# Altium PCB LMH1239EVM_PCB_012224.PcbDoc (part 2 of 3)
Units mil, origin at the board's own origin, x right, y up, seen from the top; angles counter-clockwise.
Board outline 4000 x 4500 mil, 4 copper layers (Top Layer, L02_GND, L03_PWR, Bottom Layer), stack 61.395 mil thick; 161 components, 103 nets, 483 pads, 593 vias.
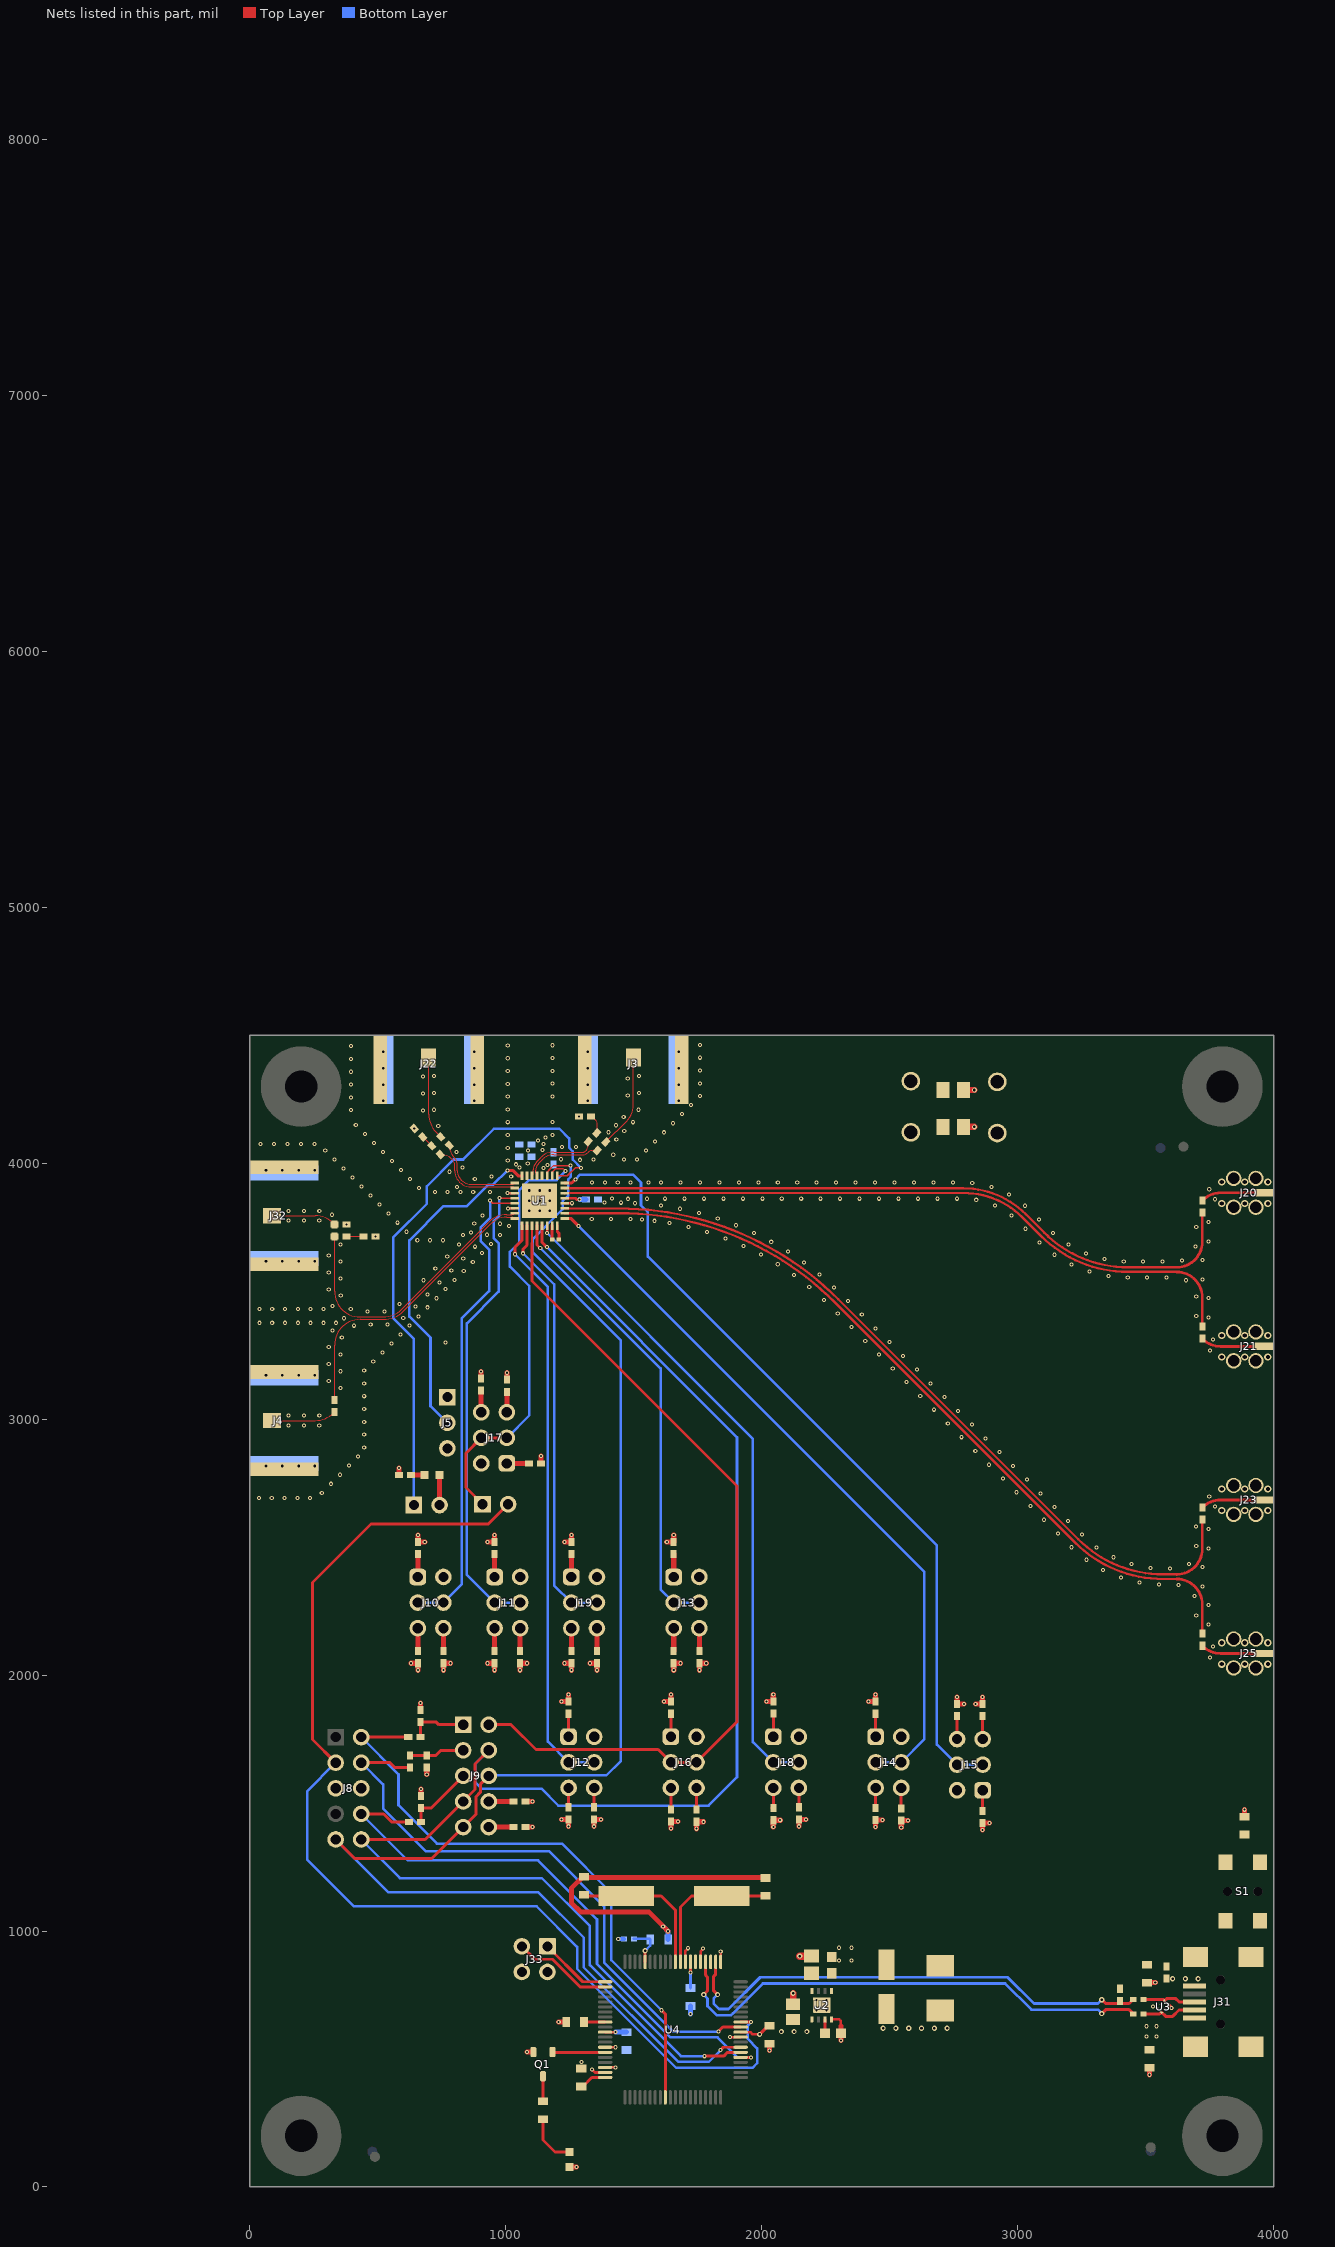
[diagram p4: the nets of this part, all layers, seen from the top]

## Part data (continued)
U3: "ESD-Protection Array for High-Speed Data Interfaces, 4 Channels, -40 to +85 degC, 6-pin SON (DRY), Green (RoHS & no Sb/Br)", Alternate Manufacturer="Texas Instruments", Alternate PartNumber=Equivalent, Breakdown Voltage(Min)(V)=6, IO Capacitance(Typ)(pF)=1.6, IO Leakage Current(nA)=1, Supplier Part Number 1=296-23618-2-ND
U4: "25 MHz Mixed Signal Microcontroller with 128 KB Flash, 8192 B SRAM and 63 GPIOs, -40 to 85 degC, 80-pin QFP (PN), Green (RoHS & no Sb/Br)", Alternate Manufacturer="Texas Instruments", Alternate PartNumber=Equivalent, Frequency(MHz)=25, Pin/Package="0DIESALE, 80LQFP", Temp Sensor=Yes
Y1: "Crystal, 24.000MHz, 20pF, SMD", Frequency=24MHz, Frequency Stability=±50ppm, Manufacturer="ECS Inc.", Supplier Part Number 1=XC1255CT-ND
ZZ2 ZZ3 ZZ4 ZZ5 ZZ6 ZZ7 ZZ8 ZZ9 ZZ10 ZZ11 ZZ12 ZZ13: library part AssemblyNote, "Place Shunt JP_N on pin 1-2"

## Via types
v1: diameter 16, hole 8, Top Layer to Bottom Layer, tented both sides, 278 vias
v2: diameter 16, hole 8.1, Top Layer to Bottom Layer, tented both sides, 224 vias
v3: diameter 20, hole 10, Top Layer to Bottom Layer, tented both sides, 54 vias
v4: diameter 28, hole 16, Top Layer to Bottom Layer, tented both sides, 24 vias
v5: diameter 20, hole 10.1, Top Layer to Bottom Layer, tented both sides, 9 vias
v6: diameter 19.68, hole 7.87, Top Layer to Bottom Layer, tented both sides, 4 vias

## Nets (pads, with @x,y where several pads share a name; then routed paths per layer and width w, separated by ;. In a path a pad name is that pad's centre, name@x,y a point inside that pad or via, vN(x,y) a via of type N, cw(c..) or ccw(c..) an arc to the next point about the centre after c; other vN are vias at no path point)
3P3V: C21.2 C32.2 C34.2 D3.1 J8.5 R1.2 R2.2 R36.1 U2.1 U4.11 U4.18 U4.50 | length 358.1
  Top Layer w10: U4.18@1387.84,467.36 v1(1428.72,467.36) ; U4.11@1387.84,605.16 v1(1428.72,605.16) ; U4.50@1917.36,604.97 1955.33,604.97 1963.9,596.4 v3(1991.8,596.4)
  Top Layer w12: v3(1991.8,596.4) 2025.4,630 C34.2@2030,630
  Top Layer w20: R2.2@1077.46,1406.52 v1(1104.58,1406.52) ; R1.2@1077.46,1506.52 v1(1104.58,1506.52) ; D3.1@1249.46,77.53 v1(1276.58,77.53)
  Bottom Layer w15: v1(1439.14,969.31) R36.1@1461.26,969.31
  Bottom Layer w20: v1(1428.72,605.16) C32.2@1471.5,605.16
  other v3: 2076.5,607.4 2126.5,607.4 2176.5,607.4
DM: R31.1 U4.64 | length 1979.8
  Top Layer w11.98: v3(1773.2,751.56) 1788.24,766.6 1788.24,819.99 1780.55,827.68 U4.64@1780.55,879.76 ; v3(3328.66,677.72) 3343.7,692.75 3435.43,692.75 R31.1@3451.73,676.46
  Bottom Layer w10.57: v3(1773.2,751.56) 1788.24,736.53 1788.24,706.84 1816.54,678.53 1823.57,671.5 1880.08,671.5 1887.11,678.53 2004.1,795.52 2951.04,795.52 3053.8,692.75 3313.63,692.75 v3(3328.66,677.72)
DP: R32.1 R33.1 U4.62 | length 1940.1
  Top Layer w11.98: U4.62@1819.92,879.76 1819.92,830.85 1812.24,823.17 1812.24,766.6 v3(1827.27,751.56) ; v3(3328.66,731.79) 3343.7,716.75 3435.43,716.75 R32.1@3451.73,733.05
  Bottom Layer w10.57: v3(1827.27,751.56) 1812.24,736.53 1812.24,716.78 1833.51,695.5 1870.14,695.5 1994.15,819.52 2960.98,819.52 3063.74,716.75 3313.63,716.75 v3(3328.66,731.79)
ENABLE: J5.2 U1.32 | length 1336.5
  Top Layer w11.61: v1(1005.98,3972.78) 1026.79,3972.78 1048.01,3951.56 U1.32@1062.97,3951.56
  Bottom Layer w9.94: J5.2@771.1,2986.27 705.53,3051.84 705.53,3318.75 623.01,3401.27 623.01,3699.45 756.38,3832.81 847.91,3832.81 931.94,3916.85 950.05,3916.85 v1(1005.98,3972.78)
GND: C1.1 C2.1 C4.2 C5.2 C6.2 C7.2 C21.1 C22.2 C23.2 C24.2 C25.1 C26.1 C27.1 C28.2 C29.2 C30.1 C31.1 C32.1 C33.1 C34.1 D2.2 J1.1 J1.2 J3.2 J3.3 J3.4 J3.5 J4.2 J4.3 J4.4 J4.5 J5.3 J8.6 J10.2 J11.2 J12.2 J13.2 J14.2 J15.2 J16.2 J17.2 J18.2 J19.2 J20.2 J20.3 J20.4 J20.5 J21.2 J21.3 J21.4 J21.5 J22.2 J22.3 J22.4 J22.5 J23.2 J23.3 J23.4 J23.5 J25.2 J25.3 J25.4 J25.5 J31.5 J32.2 J32.3 J32.4 J32.5 J33.2 J33.4 Q1.2 R4.1 R6.1 R8.1 R10.1 R12.1 R14.1 R16.1 R18.1 R20.1 R25.2 R26.2 R27.2 R28.1 R29.1 R30.1 R34.1 R35.1 R40.1 R42.1 R43.2 R44.2 R45.2 R46.2 R47.2 R48.2 R49.2 R50.2 R51.2 R52.2 U1.3 U1.6 U1.20 U1.33 U2.4 U2.9 U3.3 U4.14 U4.19 U4.49 U4.61 U4.68 | length 3171
  Top Layer w10: v1(1006.89,3884.4) ccw(c1008.7,3886.2) 1008.7,3883.65 U1.3@1034.43,3883.65 ; v1(1008.61,3823.78) cw(c1010.58,3821.81) 1010.58,3824.59 U1.6@1034.43,3824.59 ; U1.20@1226.36,3844.28 1258.39,3844.28 v1(1258.46,3844.34) ; U4.14@1387.84,546.1 v1(1428.72,546.1) ; U4.68@1701.81,879.76 1701.81,923.04 v1(1711.88,933.11) ; U4.61@1839.61,879.76 v1(1839.61,920.64) ; v1(1876.48,585.47) U4.49@1917.36,585.47 ; U2.4@2272.6,655.16 2302.74,655.16 2309.3,648.6 2309.3,630.3
  Top Layer w11.61: v1(1335.99,459.67) 1347.98,447.68 U4.19@1387.84,447.68
  Top Layer w15: U3.3@3590.25,710.52 v1(3601.29,699.48)
  Top Layer w20: v1(628.85,2046.6) R4.1@655.97,2046.6 v1(655.97,2019.48) ; R25.2@665.85,1863.72 v1(665.85,1890.84) ; R27.2@668.61,1527.74 v1(668.61,1554.86) ; v1(690.85,1612.39) R26.2@690.85,1639.51 ; v1(755.97,2019.48) R43.2@755.97,2046.6 v1(783.09,2046.6) ; R50.2@902.95,3159.68 v1(902.95,3186.8) ; v1(928.85,2046.6) R6.1@955.97,2046.6 v1(955.97,2019.48) ; R18.1@1003.78,3154.68 v1(1003.78,3181.8) ; v1(1055.97,2019.48) R44.2@1055.97,2046.6 v1(1083.09,2046.6) ; v1(1082.84,527.24) Q1.2@1107.6,527.24 ; v1(1206.5,644.53) C31.1@1235.35,644.53 ; v1(1217.88,1436.68) R8.1@1245,1436.68 v1(1245,1409.56) ; v1(1228.85,2046.6) R42.1@1255.97,2046.6 v1(1255.97,2019.48) ; v1(1328.85,2046.6) R52.2@1355.97,2046.6 v1(1355.97,2019.48) ; v1(1345,1409.56) R45.2@1345,1436.68 v1(1372.12,1436.68) ; v1(1634.06,999.31) v1(1614.88,1018.49) 1558.21,1075.15 1291.7,1075.15 1255.97,1110.89 1255.97,1167.49 1300.35,1211.88 C28.2@1305.35,1211.88 1307.54,1209.69 2011.95,1209.69 C29.2@2014.14,1207.51 ; v1(1645,1401.43) R16.1@1645,1428.56 v1(1672.12,1428.56) ; v1(1655.97,2019.48) R10.1@1655.97,2046.6 v1(1683.09,2046.6) ; v1(1745,1400.06) R49.2@1745,1427.18 v1(1772.12,1427.18) ; v1(1755.97,2019.48) R46.2@1755.97,2046.6 v1(1783.09,2046.6) ; v1(2030,532.88) C34.1@2030,560 ; v1(2045,1406.12) R20.1@2045,1433.24 v1(2072.12,1433.24) ; v1(2145.03,1409.56) R51.2@2145.03,1436.68 v1(2172.15,1436.68) ; v1(2310,573.15) C24.2@2310,600.27 2310,629.6 ; v1(2443.98,1406.43) R12.1@2443.98,1433.56 v1(2471.1,1433.56) ; v1(2545,1405.06) R47.2@2545,1432.18 v1(2572.12,1432.18) ; v1(2763.21,1914.7) R48.2@2763.21,1887.58 v1(2790.33,1887.58) ; v1(2836.09,1887.58) R14.1@2863.21,1887.58 v1(2863.21,1914.7) ; R35.1@3505.49,798.69 v1(3537.61,798.69) ; v1(3515.24,438.58) C25.1@3515.24,465.7 ; C26.1@3886.19,1447.18 v1(3886.19,1474.3)
  Top Layer w25: C21.1@2122.28,714.21 v3(2122.28,756.98)
  Top Layer w30: v3(2148.3,902.2) C23.2@2194.21,902.2
  Bottom Layer w20: v1(1614.88,1018.49) v1(1634.06,999.31) C30.1@1634.06,967.19 ; v1(1721.5,675.48) C27.1@1721.5,707.6
  other v1: 1295,488.03 35.12,2691.71 85.12,2691.71 135.12,2691.71 185.12,2691.71 235.12,2691.71 280.69,2712.61 316.04,2747.96 351.4,2783.32 386.75,2818.67 422.11,2854.03 446.48,2890.19 446.48,2940.19 150.68,2976.04 210.68,2976.04 270.68,2976.04 446.48,2990.19 150.92,3014.28 210.92,3014.28 270.92,3014.28 446.48,3040.19 446.48,3090.19 446.48,3140.19 446.48,3190.19 481.84,3225.55 517.19,3260.9 552.55,3296.26 764.1,3299.38 587.9,3331.61 623.26,3366.97 36.98,3377.13 86.98,3377.13 136.98,3377.13 186.98,3377.13 236.98,3377.13 286.98,3377.13 336.98,3377.13 658.61,3402.32 36.98,3431.25 86.98,3431.25 136.98,3431.25 186.98,3431.25 236.98,3431.25 286.98,3431.25 693.97,3437.68 729.33,3473.03 764.68,3508.39 800.04,3543.74 835.39,3579.1 870.75,3614.46 906.1,3649.81 941.46,3685.17 653.83,3699.68 703.83,3699.68 753.83,3699.68 491.26,3714.64 832.3,3720.07 976.81,3720.52 612.47,3732.77 1012.17,3755.88 377.8,3761.88 876.51,3764.48 577.11,3768.13 1580.3,3775.72 150.68,3776.04 210.68,3776.04 270.68,3776.04 1531.42,3780.07 908.47,3796.44 541.75,3803.48 150.92,3814.28 210.92,3814.28 270.92,3814.28 506.4,3838.84 1504.21,3844.31 1386.1,3846.43 1450.02,3846.31 1477.96,3861.64 1414.95,3862.08 471.04,3874.19 722.4,3887.93 772.4,3887.93 822.4,3887.93 661.01,3903.25 435.69,3909.55 1337.25,3925.02 1387.25,3925.02 1437.25,3925.02 1487.25,3925.02 1556.62,3925.02 625.65,3938.6 400.33,3944.91 1020.92,3948.86 590.3,3973.96 364.98,3980.26 1085.54,3999.7 554.94,4009.31 1007.39,4010.88 329.62,4015.62 1461.79,4015.44 1511.79,4015.44 519.59,4044.67 1086.34,4050.21 1547.15,4050.8 294.27,4050.97 1007.39,4060.88 1219.44,4064.29 41.76,4075.76 94.44,4075.76 147.13,4075.76 199.82,4075.76 252.51,4075.76 1146.66,4076.22 484.23,4080.02 1582.5,4086.15 1125.49,4088.95 1431.49,4093.75 1154.75,4101.91 1007.39,4110.88 1182.01,4111.57 448.87,4115.38 1401.28,4121.73 1617.86,4121.51 1462.54,4125.98 641.92,4136.83 1429.8,4149.06 413.52,4150.73 1653.21,4156.86 1007.39,4160.88 1182.01,4161.57 1496.63,4160.85 1460.53,4181.51 1285.14,4183 1688.57,4192.22 395.56,4208.04 1007.39,4210.88 1723.92,4227.57 395.56,4258.04 1007.39,4260.88 1182.01,4261.57 1759.28,4262.93 395.56,4308.04 1007.39,4310.88 1182.01,4311.57 1759.28,4312.93 395.56,4358.04 1007.39,4360.88 1182.01,4361.57 1759.28,4362.93 395.56,4408.04 1007.39,4410.88 1182.01,4411.57 1759.28,4412.93 395.56,4458.04 1007.39,4460.88 1182.01,4461.57 1759.28,4462.93
  other v2: 3751.84,2069.12 3763.96,2112.47 3745.03,2198.36 3697.98,2233.03 3745.03,2274.36 3690.66,2308.68 3722.36,2346.9 3628.26,2352.07 3552.29,2353.99 3476.68,2361.71 3403.2,2381.1 3333.4,2411.18 3595.37,2416.47 3519.42,2419.17 3722.31,2422.9 3444.85,2433.84 3669.26,2434.26 3268.69,2451.04 3373.85,2460.95 3745.03,2495.43 3308.47,2499.7 3210.63,2500.08 3697.98,2504.63 3250.73,2549.11 3156.86,2553.79 3745.03,2571.43 3696.51,2580.61 3196.99,2602.85 3103.12,2607.53 3143.25,2656.59 3770.78,2659.83 3049.38,2661.27 3748.71,2699.05 3089.51,2710.33 2995.64,2715.01 3035.77,2764.07 2941.9,2768.75 2982.03,2817.81 2888.16,2822.49 2928.29,2871.55 2834.42,2876.23 2874.55,2925.29 2780.68,2929.97 2820.81,2979.03 2726.94,2983.71 2767.07,3032.77 2673.2,3037.45 2713.32,3086.51 2619.46,3091.19 353.24,3121.73 2659.58,3140.25 2565.72,3144.93 307.88,3150.1 353.24,3187.73 2605.84,3193.99 2511.98,3198.67 307.88,3216.1 2552.1,3247.73 2458.24,3252.41 353.24,3253.73 3751.84,3269.12 307.88,3282.1 2498.36,3301.47 2404.5,3306.15 3763.96,3312.47 358.83,3319.49 321.77,3346.62 2444.62,3355.21 2350.76,3359.89 405.97,3365.69 471.83,3369.93 537.82,3370.94 366.94,3394.75 599.15,3395.34 3745.03,3398.36 3697.98,3403.06 2390.88,3408.95 2297.02,3413.63 459.04,3420.43 525.04,3420.73 393.94,3431.28 646.75,3441.06 322.03,3443.12 584.23,3449.94 2337.14,3462.69 2242.76,3466.84 3745.03,3474.36 3697.99,3479.06 354.73,3484.38 693.42,3487.73 307.88,3507.58 2282.6,3515.62 2185.69,3517.04 740.09,3534.4 677.56,3543.28 3657.48,3543.36 3722.36,3546.9 353.24,3550.36 3430.15,3553.35 3506.15,3553.4 3582.15,3553.4 3354.39,3559.5 2125.55,3563.5 2225.44,3565.7 307.88,3573.58 3280.39,3576.8 786.76,3581.06 724.23,3589.95 3209.74,3604.8 2062.45,3605.87 2165.32,3612.19 353.24,3616.36 3490.55,3616.47 3566.55,3616.47 3414.55,3616.88 3642.45,3620.42 3722.31,3622.9 3339.13,3626.24 833.43,3627.73 770.9,3636.61 307.88,3639.58 1996.6,3643.81 3144.08,3643.07 3266.44,3648.43 2102.47,3654.93 880.1,3674.4 3695.56,3674.78 1928.46,3677.47 353.24,3682.36 3198.65,3682.79 817.57,3683.28 3085.28,3691.22 2037.06,3693.62 3745.03,3695.43 1858.32,3706.74 926.77,3721.07 1969.29,3728.03 3137.79,3728.31 864.24,3729.95 1786.46,3731.47 3031.18,3744.6 3697.98,3750.75 1713.17,3751.58 1899.56,3758.24 976.87,3764.03 1638.75,3766.98 3745.03,3771.43 3083.49,3781.48 1487.6,3782.29 1335.6,3783.22 1411.6,3783.22 1828.1,3784.14 2975.97,3796.84 320.02,3799.35 1755.2,3805.62 1681.13,3822.61 3028.94,3834.4 1606.15,3835.03 2910.85,3836.01 2838.03,3857.75 3770.78,3859.83 1551.88,3861.68 1622.14,3861.96 1698.14,3861.96 1774.14,3861.96 1850.14,3861.96 1926.14,3861.96 2002.14,3861.96 2078.14,3861.96 2154.14,3861.96 2230.14,3861.96 2306.14,3861.96 2382.14,3861.96 2458.14,3861.96 2534.14,3861.96 2610.14,3861.96 2686.14,3861.96 2762.14,3861.96 2966.88,3878.26 872.4,3887.93 938.4,3887.93 3748.71,3899.05 809.57,3908.16 2897.11,3908.41 2822.6,3923.4 1606.62,3925.02 1682.62,3925.02 1758.62,3925.02 1834.62,3925.02 1910.62,3925.02 1986.62,3925.02 2062.62,3925.02 2138.62,3925.02 2214.62,3925.02 2290.62,3925.02 2366.62,3925.02 2442.62,3925.02 2518.62,3925.02 2594.62,3925.02 2670.62,3925.02 2746.62,3925.02 878.57,3938.42 943.83,3948.31 780.17,3967.24 830.47,3983.61 1289.14,4014.04 1342.72,4015.38 1215.29,4016.21 1419.5,4033.61 806.73,4045.2 1142.53,4052.8 1273.48,4064.54 735.9,4145.66 676.42,4207.17 719.82,4209.67 1518.33,4209.69 1476.42,4265.49 676.42,4273.17 719.82,4275.67 1519.82,4275.67 1476.42,4331.49 676.42,4339.17 719.82,4341.67 1519.82,4341.67
  other v3: 2474.3,620.2 2524.3,620.2 2574.3,620.2 2624.3,620.2 2674.3,620.2 2724.3,620.2 3605.3,813.7 3655.3,813.7 3705.3,813.7 62.61,2817.48 126.39,2817.48 190.16,2817.48 253.94,2817.48 62.61,3172.89 126.39,3172.89 190.16,3172.89 253.94,3172.89 62.61,3617.48 126.39,3617.48 190.16,3617.48 253.94,3617.48 62.61,3972.89 126.39,3972.89 190.16,3972.89 253.94,3972.89 520.41,4244.1 875.82,4244.1 1320.41,4244.1 1675.82,4244.1 520.41,4307.87 875.82,4307.87 1320.41,4307.87 1675.82,4307.87 520.41,4371.65 875.82,4371.65 1320.41,4371.65 1675.82,4371.65 520.41,4435.42 875.82,4435.42 1320.41,4435.42 1675.82,4435.42
  other v4: 3797.5,2042.94 3887.5,2042.94 3977.5,2042.94 3797.5,2126.94 3887.5,2126.94 3977.5,2126.94 3797.5,2642.94 3887.5,2642.94 3977.5,2642.94 3797.5,2726.94 3887.5,2726.94 3977.5,2726.94 3797.5,3242.93 3887.5,3242.93 3977.5,3242.93 3797.5,3326.93 3887.5,3326.93 3977.5,3326.93 3797.5,3842.93 3887.5,3842.93 3977.5,3842.93 3797.5,3926.93 3887.5,3926.93 3977.5,3926.93
  other v5: 1091.87,3814.12 1131.87,3814.12 1171.87,3814.12 1091.87,3854.12 1131.87,3854.12 1171.87,3854.12 1091.87,3894.12 1131.87,3894.12 1171.87,3894.12
  other v6: 2214.53,690.59 2253.9,690.59 2214.53,729.96 2253.9,729.96
LOCK_N: J7.1 U1.25 | length 2238.9
  Top Layer w6: U1.25@1200.77,3951.56 1240.1,3951.56 1270.71,3982.17 v1(1294.33,3982.17)
  Bottom Layer w9.94: J7.1@640.74,2664.85 640.74,3314.45 560.61,3394.57 560.61,3711.58 690.88,3841.85 690.88,3910.45 795.66,4015.23 832.79,4015.23 953.01,4135.45 1208.91,4135.45 1247,4097.36 1247,4061.31 1261.45,4046.87 1261.45,4015.06 v1(1294.33,3982.17)
LOOP_BW_SEL: J11.3 J11.4 U1.4 | length 1852.2
  Top Layer w6: v1(974.74,3863.96) U1.4@1034.43,3863.96
  Bottom Layer w9.94: v1(974.74,3863.96) 974.74,3796.29 953.36,3774.91 953.36,3706.84 971.67,3688.53 971.67,3498.53 847.95,3374.81 847.95,2391.87 J11.3@955.97,2283.85 J11.4@1055.97,2283.85
MISO: J6.2 J8.3 U4.52 | length 4433.6
  Top Layer w11.56: U4.52@1917.36,644.53 v1(1958.24,644.53)
  Top Layer w11.61: J8.3@334.99,1658.01 244.46,1748.54 244.46,2362.36 472.61,2590.51 931.18,2590.51 J6.2@1008.78,2668.11
  Bottom Layer w9.94: J8.3@334.99,1658.01 223.05,1546.08 223.05,1279.12 405.79,1096.38 1120.74,1096.38 1278.84,938.28 1278.84,852.87 1665.87,465.84 1964.37,465.84 1982.15,483.63 1982.15,541.91 1945.6,578.46 1945.6,631.88 v1(1958.24,644.53)
MISO_ADDR1: J6.1 J17.3 J17.4 U1.26 | length 1749.9
  Top Layer w6: U1.26@1181.08,3951.56 1181.08,3966.84 1192.74,3978.51 1224.92,3978.51 v1(1233.36,3970.07)
  Top Layer w11.61: J6.1@908.78,2668.11 843.9,2732.98 843.9,2867.68 J17.4@903.78,2927.55 J17.3@1003.78,2927.55
  Bottom Layer w9.94: J17.3@1003.78,2927.55 1091.36,3015.13 1091.36,3521.65 1015.97,3597.04 1015.97,3654.73 1052.44,3691.21 1052.44,3896.39 1090.65,3934.59 1197.89,3934.59 v1(1233.36,3970.07)
MODE_SEL: J13.3 J13.4 U1.12 | length 1797
  Top Layer w11.61: U1.12@1122.03,3759.63 U1.12@1122.03,3756.68 1122.03,3681.45 v1(1134.28,3669.19)
  Bottom Layer w9.94: v1(1134.28,3669.19) 1604.82,3198.65 1604.82,2334.99 J13.3@1655.97,2283.85 J13.4@1755.97,2283.85
MOSI: J8.4 R23.1 U4.51 | length 2306.3
  Top Layer w11.61: J8.4@434.99,1658.01 547.22,1658.01 565.72,1639.51 R23.1@625.1,1639.51 ; v1(1830.16,607.38) 1847.62,624.84 U4.51@1917.36,624.84
  Bottom Layer w9.94: J8.4@434.99,1658.01 520.04,1572.96 520.04,1478.93 686.7,1312.27 1168.67,1312.27 1384.33,1096.62 1384.33,876.99 1653.94,607.38 v1(1830.16,607.38)
MOSI_SDA: J8.10 J9.4 J9.7 U1.13 U4.46 | length 6357.4
  Top Layer w11.61: J8.10@434.99,1358.01 684.7,1358.01 J9.7@833.21,1506.52 879.83,1553.14 879.83,1653.14 J9.4@933.21,1706.52 ; U1.13@1141.71,3759.63 U1.13@1141.71,3756.68 1141.71,3691.03 v1(1160.2,3672.53) ; v1(1775.7,511.03) 1851.05,511.03 1866.44,526.42 U4.46@1917.36,526.42
  Bottom Layer w9.94: J8.10@434.99,1358.01 585.93,1207.07 1140.19,1207.07 1328.14,1019.12 1328.14,866.7 1683.81,511.03 v1(1775.7,511.03) ; J9.4@933.21,1706.52 879.83,1653.14 879.83,1582.12 905.24,1556.71 1138.42,1556.71 1204.68,1490.45 1792.09,1490.45 1903.19,1601.55 1903.19,2929.55 v1(1160.2,3672.53)
NetC3_2: C3.2 R28.2 | length 49.4
  Top Layer w4.3: R28.2@675.33,4103.42 C3.2@710.26,4068.49
NetC8_1: C8.1 U1.15 | length 56.8
  Top Layer w11.61: C8.1@1181.08,3702.83 U1.15@1181.08,3756.68 U1.15@1181.08,3759.63
NetC8_2: C8.2 U1.16 | length 56.5
  Top Layer w11.61: U1.16@1200.77,3756.68 1200.77,3733.63 1207.07,3727.33 C8.2@1207.07,3702.83
NetC9_2: C9.2 R29.2 | length 76.3
  Top Layer w4.3: R29.2@1332.38,4183 cw(c1332.38,4171.85) 1340.27,4179.73 1351,4169 cw(c1334.1,4152.09) 1358,4152.09 1358,4125.83 cw(c1348.64,4125.83) C9.2@1355.26,4119.21
NetC10_1: C10.1 J20.1 | length 249.1
  Top Layer w10.96: C10.1@3721.5,3854.93 3722.21,3855.65 cw(c3792.92,3784.93) 3792.92,3884.93 J20.1@3962.5,3884.93
NetC11_1: C11.1 J21.1 | length 249.1
  Top Layer w10.96: C11.1@3721.5,3314.93 3722.21,3314.22 ccw(c3792.92,3384.93) 3792.92,3284.93 J21.1@3962.5,3284.93
NetC13_1_2: C13_1.2 R40.2 | length 66.2
  Top Layer w4.3: C13_1.2@377.8,3714.64 R40.2@444.01,3714.64
NetC13_2: C13.2 J32.1 R30.2 | length 253.4
  Top Layer w4.3: J32.1@86.61,3795.18 255.84,3795.18 cw(c255.84,3695.18) 326.55,3765.89 C13.2@330.56,3761.88
NetC14_1: C14.1 J23.1 | length 249.1
  Top Layer w10.96: C14.1@3721.5,2654.94 3722.21,2655.65 cw(c3792.92,2584.94) 3792.92,2684.94 J23.1@3962.5,2684.94
NetC15_1: C15.1 J25.1 | length 249.1
  Top Layer w10.96: C15.1@3721.5,2114.94 3722.21,2114.22 ccw(c3792.92,2184.94) 3792.92,2084.94 J25.1@3962.5,2084.94
NetC16_2: C16.2 J22.1 | length 324.9
  Top Layer w4.3: J22.1@698.12,4413.38 698.12,4192.77 ccw(c798.12,4192.77) 727.41,4122.06 C16.2@745.62,4103.85
NetC17_2: C17.2 J4.1 | length 253.4
  Top Layer w4.3: J4.1@86.62,2995.18 255.84,2995.18 ccw(c255.84,3095.18) 326.55,3024.47 C17.2@330.56,3028.48
NetC18_2: C18.2 J3.1 | length 370.2
  Top Layer w4.3: C18.2@1390.62,4083.85 1471.88,4165.12 ccw(c1408.54,4228.46) 1498.12,4228.46 J3.1@1498.12,4413.38
NetC23_1: C23.1 FB1.2 U2.5 U2.8
NetC24_1: C24.1 U2.3 | length 54.9
  Top Layer w11.61: C24.1@2247.01,600.27 U2.3@2247.01,655.16
NetC27_2: C27.2 U4.67 | length 102.2
  Top Layer w11.56: v1(1721.5,838.2) U4.67@1721.5,879.76
  Bottom Layer w9.94: C27.2@1721.5,777.6 v1(1721.5,838.2)
NetC28_1: C28.1 U4.70 Y1.2 | length 584
  Top Layer w11.61: C28.1@1305.35,1141.88 1309.72,1137.51 Y1.2@1470.12,1137.51 1606.79,1137.51 1662.44,1081.86 U4.70@1662.44,879.76
NetC29_1: C29.1 U4.69 Y1.1 | length 564.3
  Top Layer w11.61: U4.69@1682.13,879.76 1682.13,1094.13 1725.51,1137.51 Y1.1@1844.14,1137.51 C29.1@2014.14,1137.51
NetC30_2: C30.2 R36.2 U4.76 | length 159.9
  Top Layer w11.56: U4.76@1544.33,879.76 v3(1544.33,923)
  Bottom Layer w9.94: R36.2@1500.63,969.31 1561.93,969.31 C30.2@1564.06,967.19 1564.06,942.72 v3(1544.33,923)
NetC31_2: C31.2 U4.9 | length 82.5
  Top Layer w11.56: C31.2@1305.35,644.53 U4.9@1387.84,644.53
NetC33_2: C33.2 U4.20 | length 107.3
  Top Layer w11.61: C33.2@1295,392.99 1300.99,392.99 1335.99,427.99 U4.20@1387.84,427.99
NetD1_1: D1.1 R21.2 | length 52.2
  Top Layer w20: R21.2@629.47,2782.36 D1.1@681.69,2782.36
NetD1_2: D1.2 J7.2 | length 117.5
  Top Layer w20: J7.2@740.74,2664.85 D1.2@740.74,2782.36
NetD3_2: D3.2 R37.2 | length 205.4
  Top Layer w11.61: R37.2@1145,265 1145,183.43 1191.84,136.59 D3.2@1249.46,136.59
NetJ9_1: J9.1 R22.2 R25.1 | length 229.9
  Top Layer w11.61: R22.2@665.85,1758.01 R25.1@665.85,1816.48 728.25,1816.48 738.21,1806.52 J9.1@833.21,1806.52
NetJ9_3: J9.3 R23.2 R26.1 | length 216.3
  Top Layer w11.61: R23.2@625.1,1686.75 R26.1@690.85,1686.75 726.85,1686.75 746.62,1706.52 J9.3@833.21,1706.52
NetJ9_5: J9.5 R24.2 R27.1 | length 271.8
  Top Layer w11.61: R24.2@668.61,1425.5 R27.1@668.61,1480.5 707.18,1480.5 J9.5@833.21,1606.52
NetJ9_8: J9.8 R1.1 | length 97
  Top Layer w20: J9.8@933.21,1506.52 R1.1@1030.21,1506.52
NetJ9_10: J9.10 R2.1 | length 97
  Top Layer w20: J9.10@933.21,1406.52 R2.1@1030.21,1406.52
NetJ10_1: J10.1 R3.2 | length 90
  Top Layer w20: J10.1@655.97,2383.85 R3.2@655.97,2473.85
NetJ10_5: J10.5 R4.2 | length 90
  Top Layer w20: R4.2@655.97,2093.85 J10.5@655.97,2183.85
NetJ10_6: J10.6 R43.1 | length 90
  Top Layer w20: R43.1@755.97,2093.85 J10.6@755.97,2183.85
NetJ11_1: J11.1 R5.2 | length 90
  Top Layer w20: J11.1@955.97,2383.85 R5.2@955.97,2473.85
NetJ11_5: J11.5 R6.2 | length 90
  Top Layer w20: R6.2@955.97,2093.85 J11.5@955.97,2183.85
NetJ11_6: J11.6 R44.1 | length 90
  Top Layer w20: R44.1@1055.97,2093.85 J11.6@1055.97,2183.85
NetJ12_1: J12.1 R7.2 | length 90
  Top Layer w11.61: J12.1@1245,1759.42 R7.2@1245,1849.42
NetJ12_5: J12.5 R8.2 | length 75.5
  Top Layer w11.61: R8.2@1245,1483.92 J12.5@1245,1559.42
NetJ12_6: J12.6 R45.1 | length 75.5
  Top Layer w11.61: R45.1@1345,1483.92 J12.6@1345,1559.42
NetJ13_1: J13.1 R9.2 | length 90
  Top Layer w20: J13.1@1655.97,2383.85 R9.2@1655.97,2473.85
NetJ13_5: J13.5 R10.2 | length 90
  Top Layer w20: R10.2@1655.97,2093.85 J13.5@1655.97,2183.85
NetJ13_6: J13.6 R46.1 | length 90
  Top Layer w20: R46.1@1755.97,2093.85 J13.6@1755.97,2183.85
NetJ14_1: J14.1 R11.2 | length 90
  Top Layer w11.61: J14.1@2445,1759.42 R11.2@2445,1849.42
NetJ14_5: J14.5 R12.2 | length 79
  Top Layer w11.61: R12.2@2445,1481.82 J14.5@2445,1559.42
  Top Layer w20: R12.2@2443.98,1480.8 R12.2@2445,1481.82
NetJ14_6: J14.6 R47.1 | length 80
  Top Layer w11.61: R47.1@2545,1479.42 J14.6@2545,1559.42
NetJ15_1: J15.1 R13.2 | length 80.9
  Top Layer w11.61: R13.2@2863.21,1469.42 J15.1@2863.21,1550.33
NetJ15_5: J15.5 R14.2 | length 90
  Top Layer w11.61: J15.5@2863.21,1750.33 R14.2@2863.21,1840.33
NetJ15_6: J15.6 R48.1 | length 90
  Top Layer w11.61: J15.6@2763.21,1750.33 R48.1@2763.21,1840.33
NetJ16_1: J16.1 R15.2 | length 90
  Top Layer w11.61: J16.1@1645,1759.42 R15.2@1645,1849.42
NetJ16_5: J16.5 R16.2 | length 83.6
  Top Layer w11.61: R16.2@1645,1475.8 J16.5@1645,1559.42
NetJ16_6: J16.6 R49.1 | length 85
  Top Layer w11.61: R49.1@1745,1474.42 J16.6@1745,1559.42
NetJ17_1: J17.1 R17.2 | length 86.4
  Top Layer w20: J17.1@1003.78,2827.29 R17.2@1090.17,2827.29
NetJ17_5: J17.5 R18.2 | length 79.9
  Top Layer w20: J17.5@1003.78,3027.55 R18.2@1003.78,3107.43
NetJ17_6: J17.6 R50.1 | length 84.9
  Top Layer w20: J17.6@902.95,3027.55 R50.1@902.95,3112.43
NetJ18_1: J18.1 R19.2 | length 91.2
  Top Layer w11.61: J18.1@2045,1759.42 R19.2@2045,1850.6
NetJ18_5: J18.5 R20.2 | length 78.9
  Top Layer w11.61: R20.2@2045,1480.49 J18.5@2045,1559.42
NetJ18_6: J18.6 R51.1 | length 75.5
  Top Layer w11.61: R51.1@2145.03,1483.92 J18.6@2145,1559.42
NetJ19_1: J19.1 R41.2 | length 90
  Top Layer w20: J19.1@1255.97,2383.85 R41.2@1255.97,2473.85
NetJ19_5: J19.5 R42.2 | length 90
  Top Layer w20: R42.2@1255.97,2093.85 J19.5@1255.97,2183.85
NetJ19_6: J19.6 R52.1 | length 90
  Top Layer w20: R52.1@1355.97,2093.85 J19.6@1355.97,2183.85
NetJ31_2: J31.2 R31.2 U3.1 | length 219.8
  Top Layer w11.98: R31.2@3491.1,676.46 3554.79,676.46 U3.1@3561.71,683.38 3578.39,666.7 3605.6,666.7 3630.36,691.46 J31.2@3690.91,691.46
NetJ31_3: J31.3 R32.2 U3.4 | length 211.6
  Top Layer w11.98: R32.2@3491.1,733.05 3491.1,733.42 3567.35,733.42 U3.4@3573.54,727.23 3582.12,735.8 3618,735.8 3630.85,722.95 J31.3@3690.91,722.95
NetJ31_6: J31.6 J31.7 J31.8 J31.9 R34.2
NetJ33_1: J33.1 U4.1 | length 282.5
  Top Layer w11.61: J33.1@1162.6,940.2 1300.79,802.01 U4.1@1387.84,802.01
NetJ33_3: J33.3 U4.2 | length 390.6
  Top Layer w11.61: J33.3@1062.6,940.2 1112.8,890 1182,890 1289.68,782.32 U4.2@1387.84,782.32
NetQ1_1: Q1.1 U4.15 | length 205.8
  Top Layer w11.61: Q1.1@1182.4,527.24 1183.23,526.42 U4.15@1387.84,526.42
NetQ1_3: Q1.3 R37.1 | length 97.8
  Top Layer w11.61: R37.1@1145,335 Q1.3@1145,432.76
OUT0_N: C11.2 U1.22 | length 2756.5
  Top Layer w9.13: U1.22@1229.31,3883.65 1230.15,3884.49 2788.17,3884.49 cw(c2788.17,3558.6) 3018.61,3789.04 3090.95,3716.7 ccw(c3430.79,4056.54) 3430.79,3575.93 3621.5,3575.93
  Top Layer w10.96: 3621.5,3575.93 cw(c3621.5,3475.93) 3721.5,3475.93 C11.2@3721.5,3362.18
OUT0_OUT1_SEL: J10.3 J10.4 U1.5 | length 1873.2
  Top Layer w6: v1(938.59,3854.71) 949.02,3844.28 U1.5@1034.43,3844.28
  Bottom Layer w9.94: J10.3@655.97,2283.85 J10.4@755.97,2283.85 826.96,2354.84 826.96,3393.82 934.21,3501.07 934.21,3663.27 902.14,3695.34 902.14,3750.59 938.59,3787.04 v1(938.59,3854.71)
OUT0_P: C10.2 U1.23 | length 2756.5
  Top Layer w9.13: U1.23@1229.31,3903.33 1230.15,3902.49 2788.22,3902.49 cw(c2788.22,3558.74) 3031.3,3801.81 3103.65,3729.45 ccw(c3430.82,4056.63) 3430.82,3593.93 3621.5,3593.93
  Top Layer w10.96: 3621.5,3593.93 ccw(c3621.5,3693.93) 3721.5,3693.93 C10.2@3721.5,3807.69
OUT1_N: C15.2 U1.18 | length 3183.3
  Top Layer w9.13: U1.18@1229.31,3804.91 1230.15,3805.75 1286.08,3805.75 1442.44,3805.75 cw(c1442.43,2612.33) 2286.31,3456.2 3224.01,2518.5 ccw(c3568.2,2862.69) 3568.2,2375.94 3621.5,2375.94
  Top Layer w10.96: 3621.5,2375.94 cw(c3621.5,2275.94) 3721.5,2275.94 C15.2@3721.5,2162.18
OUT1_P: C14.2 U1.19 | length 3183.3
  Top Layer w9.13: U1.19@1229.31,3824.59 1230.15,3823.75 1265.27,3823.75 1442.49,3823.75 cw(c1442.49,2612.47) 2299,3468.97 3236.71,2531.25 ccw(c3568.23,2862.77) 3568.23,2393.94 3621.5,2393.94
  Top Layer w10.96: 3621.5,2393.94 ccw(c3621.5,2493.94) 3721.5,2493.94 C14.2@3721.5,2607.69
OUT_CTRL: J14.3 J14.4 U1.17 | length 2860.2
  Top Layer w11.61: U1.17@1229.31,3785.22 1253.98,3785.22 v1(1283.23,3755.98)
  Bottom Layer w9.94: v1(1283.23,3755.98) 2635.54,2403.67 2635.54,1749.96 J14.4@2545,1659.42 J14.3@2445,1659.42
PWR: R33.2 R35.2 S1.1 S1.3 U4.63
SCK: J8.8 R24.1 U4.45 | length 2260
  Top Layer w11.61: J8.8@434.99,1458.01 522.38,1458.01 554.9,1425.5 R24.1@621.37,1425.5 ; U4.45@1917.36,506.73 v1(1958.24,506.73)
  Bottom Layer w9.94: J8.8@434.99,1458.01 616.66,1276.34 1125.55,1276.34 1356.1,1045.79 1356.1,871.76 1643.25,584.62 1827.04,584.62 1904.93,506.73 v1(1958.24,506.73)
SCK_SCL: J8.9 J9.6 J9.9 U1.27 U4.47 | length 6043.5
  Top Layer w6: U1.27@1161.4,3951.56 1161.4,3966.84 1171.84,3977.29 1185.89,3991.33 v1(1253.28,3991.33)
  Top Layer w11.61: J8.9@334.99,1358.01 409.45,1283.55 710.24,1283.55 J9.9@833.21,1406.52 884.2,1457.52 884.2,1525.95 900.38,1542.12 900.38,1573.69 J9.6@933.21,1606.52 ; v1(1838.44,535.51) 1849.04,546.1 U4.47@1917.36,546.1
  Bottom Layer w9.94: J8.9@334.99,1358.01 541.76,1151.24 1127.39,1151.24 1304.46,974.17 1304.46,858.32 1674.1,488.68 1792.88,488.68 1838.44,534.24 v1(1838.44,535.51) ; J9.6@933.21,1606.52 935.23,1608.54 1392.31,1608.54 1449.15,1665.38 1449.15,3307.64 1105.44,3651.35 1105.44,3704.69 1221.52,3820.77 1221.52,3852.18 1243.9,3874.56 1243.9,3938 1253.28,3947.39 v1(1253.28,3991.33)
SDI_IN0+: C16.1 U1.1 | length 363
  Top Layer w3.5: C16.1@779.02,4070.44 ccw(c847.31,4070.44) 799.02,4022.16 ; 799.05,4022.13 cw(c771.97,3995.11) 810.23,3995.11 810.23,3971.8 ccw(c863.57,3971.8) 825.85,3934.08 ccw(c864.26,3972.49) 864.26,3918.18 1022.74,3918.18 ccw(c1022.74,3934.71) U1.1@1034.43,3923.02
SDI_IN0-: C3.1 U1.2 | length 370.9
  Top Layer w3.5: C3.1@743.67,4035.08 cw(c743.67,3966.8) 791.95,4015.08 cw(c771.97,3995.11) 800.23,3995.11 800.23,3971.78 ccw(c863.52,3971.78) 818.76,3927.03 ccw(c864.2,3972.36) 864.2,3908.18 1022.74,3908.18 cw(c1022.74,3891.64) U1.2@1034.43,3903.33
SDI_IN1+: C18.1 U1.29 | length 297.9
  Top Layer w3.5: U1.29@1122.03,3951.56 cw(c1133.72,3963.25) 1117.18,3963.25 1117.18,3974.11 cw(c1153.75,3974.11) 1127.89,3999.96 1145.14,4017.21 cw(c1186.38,3975.98) 1186.38,4034.29 1302.6,4034.29 ccw(c1302.6,4058.85) 1319.96,4041.48 cw(c1341.6,4019.84) 1341.6,4050.45 C18.1@1357.21,4050.45
SDI_IN1-: C9.1 U1.30 | length 305.8
  Top Layer w3.5: U1.30@1102.34,3951.56 ccw(c1090.65,3963.25) 1107.18,3963.25 1107.18,3974.17 cw(c1153.6,3974.17) 1120.78,4006.99 1138.1,4024.31 cw(c1186.34,3976.07) 1186.34,4044.29 1302.6,4044.29 ccw(c1302.6,4058.85) 1312.89,4048.55 ccw(c1291.25,4070.19) 1321.85,4070.19 C9.1@1321.85,4085.8
SDI_IN_SEL: J19.3 J19.4 U1.10 | length 1660.9
  Top Layer w11.61: v1(1066.91,3648.74) 1066.91,3664.49 1082.66,3680.23 U1.10@1082.66,3756.68 U1.10@1082.66,3759.63
  Bottom Layer w9.94: v1(1066.91,3648.74) 1067.44,3648.74 1188.56,3527.62 1188.56,2351.25 J19.3@1255.97,2283.85 J19.4@1355.97,2283.85
SDI_OUT+: C17.1 U1.8 | length 1133.7
  Top Layer w3.5: 430.56,3390.18 521.71,3390.18 ccw(c521.71,3500.1) 599.42,3422.36 ; 599.44,3422.38 940.75,3763.69 cw(c1004.43,3700.01) 1004.43,3790.07 1022.74,3790.07 cw(c1022.74,3773.53) U1.8@1034.43,3785.22
  Top Layer w4.3: C17.1@330.56,3075.72 330.56,3290.18 cw(c430.56,3290.18) 379.16,3375.96 cw(c430.56,3290.18) 430.56,3390.18
SDI_OUT-: C13.1 C13_1.1 U1.7 | length 1133.7
  Top Layer w3.5: 430.56,3400.18 521.68,3400.18 ccw(c521.68,3500.18) 592.38,3429.46 ; 592.39,3429.47 933.7,3770.78 cw(c1004.41,3700.07) 1004.41,3800.07 1022.74,3800.07 ccw(c1022.74,3816.6) U1.7@1034.43,3804.91
  Top Layer w4.3: C13_1.1@330.56,3714.64 330.56,3500.18 ccw(c430.56,3500.18) 379.16,3414.4 ccw(c430.56,3500.18) 430.56,3400.18
SDI_OUT_ENA: J18.3 J18.4 U1.14 | length 2564.1
  Top Layer w9.94: v1@1160.92,3727.2 1161.4,3727.68 U1.14@1161.4,3756.68
  Bottom Layer w9.94: v1@1160.92,3727.2 1161.69,3727.2 1965.43,2923.46 1965.43,1738.99 J18.3@2045,1659.42 J18.4@2145,1659.42
  other v1: 1161.4,3727.2
SDI_VOD: J15.3 J15.4 U1.24 | length 3211.2
  Top Layer w11.61: U1.24@1229.31,3923.02 1257.14,3923.02 v1(1271.49,3937.37)
  Bottom Layer w9.94: v1(1271.49,3937.37) 1290.02,3955.9 1496.74,3955.9 1528.13,3924.51 1528.13,3835.8 1554.82,3809.11 1554.82,3635.71 2684.52,2506.01 2684.52,1729.03 J15.4@2763.21,1650.33 J15.3@2863.21,1650.33
SS_N_ADDR0: J9.2 J16.3 J16.4 U1.11 | length 3370.2
  Top Layer w8: 1102.34,3688.62 U1.11@1102.34,3759.63
  Top Layer w11.61: J9.2@933.21,1806.52 1020.44,1806.52 1117.69,1709.27 1595.16,1709.27 J16.3@1645,1659.42 J16.4@1745,1659.42 1903.19,1817.61 1903.19,2739.46 1102.34,3540.31 1102.34,3688.62
SSN: J8.2 R22.1 U4.29 | length 2369.5
  Top Layer w11.61: J8.2@434.99,1758.01 R22.1@618.61,1758.01 ; v1(1607.91,690.71) 1623.07,675.55 U4.29@1623.07,350.24
  Bottom Layer w9.94: J8.2@434.99,1758.01 580.45,1612.55 580.45,1492.4 730.79,1342.06 1219,1342.06 1411.84,1149.22 1411.84,886.78 v1(1607.91,690.71)
VBUS: C22.1 C25.2 D2.1 FB1.1 J31.1 U3.6 U4.65 | length 57.4
  Top Layer w10: U4.65@1760.87,879.76 1761.21,880.11 1761.21,920.57 1771.7,931.06 v1@1771.7,932.7
  other v1: 3502.8,588.1 3542.8,588.1 3502.8,628.1 3542.8,628.1 3528.1,705.6 2301.3,884.94 2351.3,884.94 1770.62,931.6 2301.3,934.94 2351.3,934.94
VDD_LDO: C6.1 C7.1 U1.31
  other v1: 1054.04,3984.68 1039.59,3996.45
VIN: C1.2 C2.2 C4.1 C5.1 J2.1 J2.2 J5.1 R3.1 R5.1 R7.1 R9.1 R11.1 R13.1 R15.1 R17.1 R19.1 R21.1 R41.1 U1.21 U1.28 | length 705.2
  Top Layer w10: U1.21@1229.31,3863.96 1229.73,3864.38 1271.36,3864.38 1276.86,3858.88
  Top Layer w20: R21.1@582.22,2782.36 v1(582.22,2809.48) ; v1(655.97,2548.21) R3.1@655.97,2521.09 v1(683.09,2521.09) ; v1(928.85,2521.09) R5.1@955.97,2521.09 v1(955.97,2548.21) ; R17.1@1137.42,2827.29 v1@1137.42,2856.54 ; v1(1217.88,1896.67) R7.1@1245,1896.67 v1(1245,1923.79) ; v1(1228.85,2521.09) R41.1@1255.97,2521.09 v1(1255.97,2548.21) ; v1(1617.88,1896.67) R15.1@1645,1896.67 v1(1645,1923.79) ; v1(1628.85,2521.09) R9.1@1655.97,2521.09 v1(1655.97,2548.21) ; v1(2017.88,1897.84) R19.1@2045,1897.84 v1(2045,1924.96) ; v1(2417.88,1896.67) R11.1@2445,1896.67 v1(2445,1923.79) ; v1(2863.21,1395.06) R13.1@2863.21,1422.18 v1(2890.33,1422.18)
  Top Layer w25: C1.2@2787.98,4142.46 v3(2830.74,4142.46) ; C2.2@2787.98,4286.67 v3(2830.74,4286.67)
  Bottom Layer w20: v1(1288.32,3858.88) C5.1@1313.38,3858.88
  other v1: 1138.05,2856.9 1147.18,3981.67 1163.22,3994.01
VOD_DEM_SEL: J12.3 J12.4 U1.9 | length 2298.2
  Top Layer w11.61: v1(1035.64,3644.96) 1035.64,3671.95 1062.97,3699.28 U1.9@1062.97,3759.63
  Bottom Layer w9.94: v1(1035.64,3644.96) 1163.94,3516.66 1163.94,1740.48 J12.3@1245,1659.42 J12.4@1345,1659.42
VUSB: C26.2 S1.2 S1.4 U4.66
pads on no net: FID1.1 FID2.1 FID3.1 FID4.1 FID5.1 FID6.1 H1.1 H2.1 H3.1 H4.1 H5.0 H6.0 H7.0 H8.0 J8.1 J8.7 J31.4 J31.10 J31.11 S1. SH-J2.0 SH-J3.0 SH-J4.0 SH-J5.0 SH-J6.0 SH-J7.0 SH-J8.0 SH-J9.0 SH-J10.0 SH-J11.0 SH-J12.0 SH-J13.0 U2.2 U2.6 U2.7 U3.2 U3.5 U4.3 U4.4 U4.5 U4.6 U4.7 U4.8 U4.10 U4.12 U4.13 U4.16 U4.17 U4.21 U4.22 U4.23 U4.24 U4.25 U4.26 U4.27 U4.28 U4.30 U4.31 U4.32 U4.33 U4.34 U4.35 U4.36 U4.37 U4.38 U4.39 U4.40 U4.41 U4.42 U4.43 U4.44 U4.48 U4.53 U4.54 U4.55 U4.56 U4.57 U4.58 U4.59 U4.60 U4.71 U4.72 U4.73 U4.74 U4.75 U4.77 U4.78 U4.79 U4.80

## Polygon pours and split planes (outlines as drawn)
GND on Bottom Layer "L02_GND-GND" (solid, remove dead copper, pour order 56): 3968,4500 0,4500 0,26 3968,26
VBUS on Bottom Layer "BOTTOM_LAYER_VBUS_P020" (solid, remove dead copper, pour order 20): 1769.68,852.97 1755.28,867.37 1755.28,934.17 1774.22,953.1 2349.52,953.1 2361.93,940.69 2361.93,873.53 2341.37,852.97
VBUS on Bottom Layer "BOTTOM_LAYER_VBUS_P049" (solid, remove dead copper, pour order 49): 3505.49,722.1 3545.2,722.1 3561.35,705.95 3561.35,587.05 3540.6,566.3 3503.1,566.3 3488.7,580.7 3488.7,705.31
GND on L03_PWR "L02_GND-GND" (solid, remove dead copper, pour order 53): 3968,4500 0,4500 0,25 3968,25
VIN on L03_PWR "L03_PWR_VIN_P041" (solid, remove dead copper, pour order 41): 2611.57,4017.57 2745,4151 2745,4283.69 2824.31,4363 3191.93,4363 3293,4261.93 3293,3308.62 3170.28,3185.9 1414.23,3185.9 1153.67,2925.35 1153.67,2710.18 1299.46,2564.39 1697.25,2564.39 2274.65,1987 2876.9,1987 2916.4,1947.49 2916.4,1388.4 2886.7,1358.7 1410.14,1358.34 558.02,2210.46 558.02,3178.86 1069.7,3690.54 1069.7,3970.33 1112.86,4013.49 1222.8,4013.49 1283.67,3952.63 1723.02,3952.63 1787.96,4017.57
3P3V on L03_PWR "L03_PWR-3P3V" (solid, remove dead copper, pour order 6): 2187.51,980.9 2288.46,879.95 2288.46,177.97 2150.26,39.76 960.56,39.76 154.93,845.39 154.93,1545.49 210.3,1600.85 1037.4,1600.85 1657.36,980.9 2164.42,980.9
GND on Top Layer "L02_GND-GND" (solid, remove dead copper, pour order 63): 3968,4500 0,4500 0,27 3968,27
VUSB on Top Layer "TOP_LAYER_VUSB_P039" (solid, remove dead copper, pour order 39): 3884,1014 3894,1004 3967,1004 3977.12,1014.12 3977.12,1368.98 3927.3,1418.8 3079.2,1418.8 2967.1,1306.7 2242.9,1306.7 2017.8,1081.6 1797.3,1081.6 1735.1,1019.4 1735.1,854.5 1738.5,851.1 1744,851.1 1747.4,854.5 1747.4,940.1 1834.3,1027 2080.9,1027 2200.06,1146.15 3467.23,1146.15 3645.07,1324 3861,1324 3884,1301
PWR on Top Layer "TOP_LAYER_PWR_P038" (solid, remove dead copper, pour order 38): 1794.1,854.6 1794.1,967.6 1835.9,1009.4 2088.4,1009.4 2191.3,1112.3 3492.9,1112.3 3681.6,1301 3838.68,1301 3845.67,1294.01 3845.67,1015.66 3830.5,1000.5 3584.2,1000.5 3530.2,946.5 3530.2,856 3522.2,848 3470.5,848 3430.5,808 3430.5,774.2 3415.4,759.1 3384.1,759.1 3372,771.2 3108.1,771.2 2847.4,1031.9 2221.2,1031.9 2134,944.7 1834.5,944.7 1806.3,916.5 1806.3,854.2 1803.1,851 1797.7,851
VIN on Top Layer "TOP_LAYER_VIN_P062" (solid, remove dead copper, pour order 62): 2758.23,4096.16 2758.23,4335.88 2785.85,4363.5 2945.32,4363.5 2965.63,4343.19 2965.63,4091.46 2940.1,4065.93 2788.45,4065.93
VBUS on Top Layer "TOP_LAYER_VBUS_P052" (solid, remove dead copper, pour order 52): 3739.38,668.86 3737.24,670.99 3635.5,670.99 3604.33,639.82 3175.62,639.82 2862.24,953.19 2268.14,953.19 2249.05,934.1 2249.05,879.11 2255.38,872.78 2322.29,872.78 2390.41,804.67 2761.63,804.67 3048.33,517.97 3552.59,517.97 3645.34,610.71 3733.21,610.71 3739.38,616.88
GND on Top Layer "TOP_LAYER_GND_P031" (solid, remove dead copper, pour order 31): 2734,4107 2708,4081 2558,4081 2519,4120 2519,4325 2556,4362 2693,4362 2734,4321
GND on Top Layer "TOP_LAYER_GND_P028" (solid, remove dead copper, pour order 28): 2090,692 2173,692 2182,683 2195,683 2201,677 2257,677 2264,670 2264,641 2287,618 2287,571 2301,557 2323,557 2338,572 2338,698 2294,742 2159,742 2130,771 2100,771 2082,753 2082,700
GND on L02_GND "L02_GND-GND" (solid, remove dead copper, pour order 54): 3968,4500 0,4500 0,25 3968,25

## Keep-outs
Keep-Out Layer:
  text ".Layer_Name" at -923,-6999.16 h60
